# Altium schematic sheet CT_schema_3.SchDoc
size 276 x 169 mm
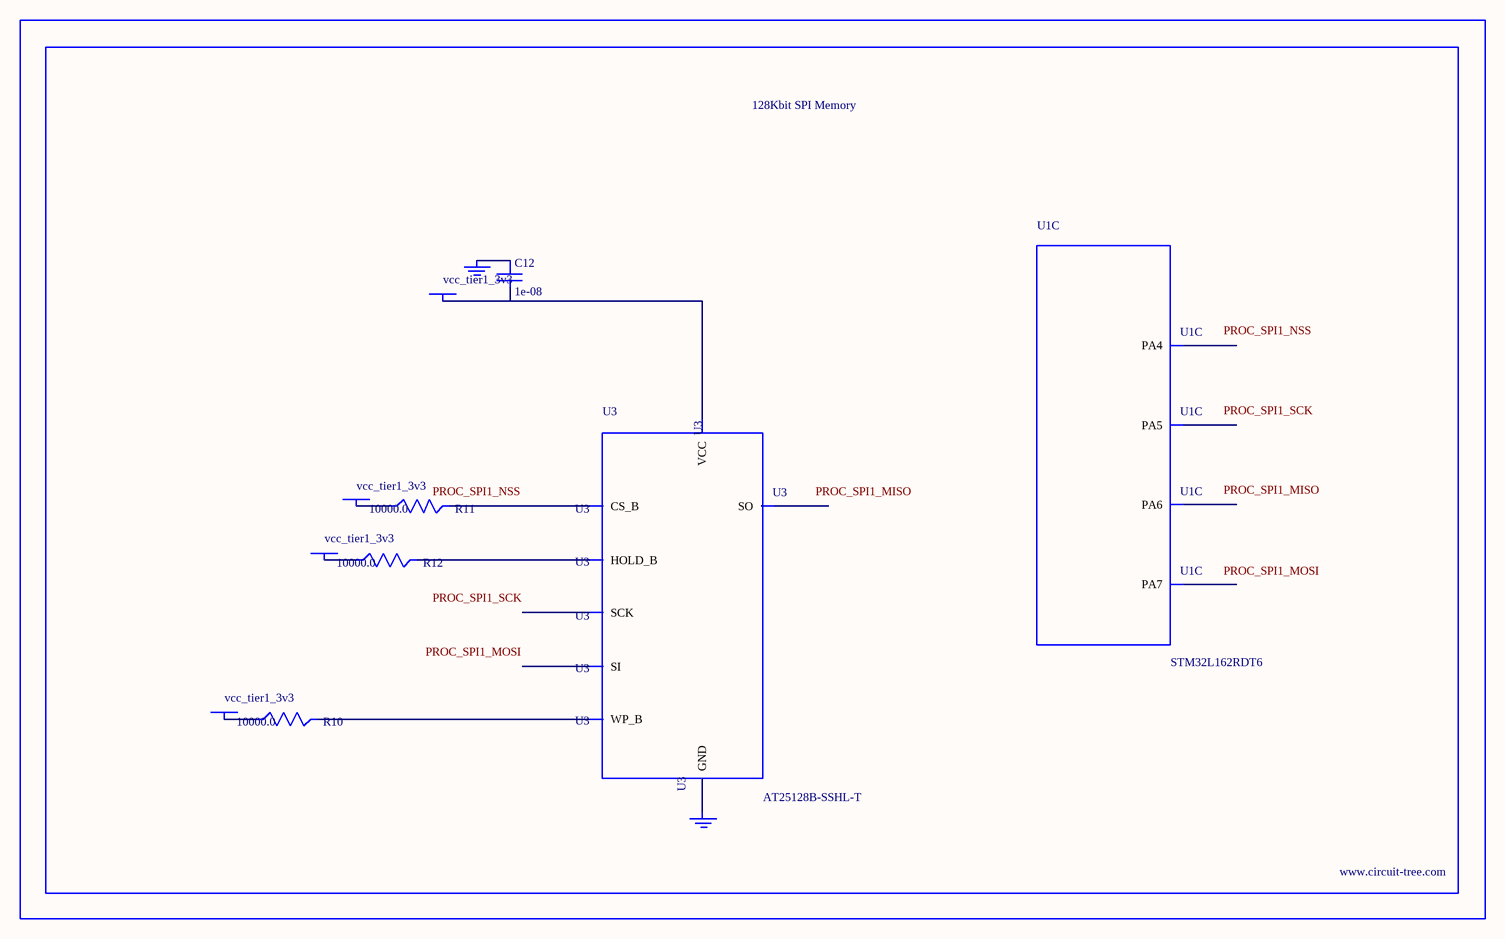
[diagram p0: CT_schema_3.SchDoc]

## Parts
BORDER2  (no value)
C12  1e-08  [C0402]
GND_INSTANCE_2_0  (no value)
GND_INSTANCE_2_1  (no value)
POWER_INSTANCE_2_0  vcc_tier1_3v3
POWER_INSTANCE_2_1  vcc_tier1_3v3
POWER_INSTANCE_2_2  vcc_tier1_3v3
POWER_INSTANCE_2_3  vcc_tier1_3v3
R10  10000.0  [R0603]
R11  10000.0  [R0603]
R12  10000.0  [R0603]
U1  STM32L162RDT6  [LQFP64]  (part C of 5)
U3  AT25128B-SSHL-T  [SOIC-8]

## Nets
NetC12_1: C12.1 GND_INSTANCE_2_0.0(GND)
NetC12_2: C12.2 POWER_INSTANCE_2_3.0(PWR) U3.8(VCC)
NetGND_INSTANCE_2_1_0: GND_INSTANCE_2_1.0(GND) U3.4(GND)
NetPOWER_INSTANCE_2_0_0: POWER_INSTANCE_2_0.0(PWR) R11.1
NetPOWER_INSTANCE_2_1_0: POWER_INSTANCE_2_1.0(PWR) R10.1
NetPOWER_INSTANCE_2_2_0: POWER_INSTANCE_2_2.0(PWR) R12.1
NetR10_2: R10.2 U3.3(WP_B)
NetR11_2: R11.2 U3.1(CS_B)
NetR12_2: R12.2 U3.7(HOLD_B)

Not connected (* = marked no-connect by the designer): U1 20(PA4) 21(PA5) 22(PA6) 23(PA7); U3 2(SO) 5(SI) 6(SCK)

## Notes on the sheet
- Labels drawn without touching a wire or pin: PROC_SPI1_MISO, PROC_SPI1_MOSI, PROC_SPI1_NSS, PROC_SPI1_SCK

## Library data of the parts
BORDER2 = BORDER_PAGE2
C12 = C0402C103K3RAC
GND_INSTANCE_2_0 GND_INSTANCE_2_1 = GND
POWER_INSTANCE_2_0-POWER_INSTANCE_2_3 = PWR
R10-R12 = RC0603JR-0710KL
